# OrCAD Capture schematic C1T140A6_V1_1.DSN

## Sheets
1 000_NOTE: title: Telink-Semi; rev: V1.1; note: C1T140A6
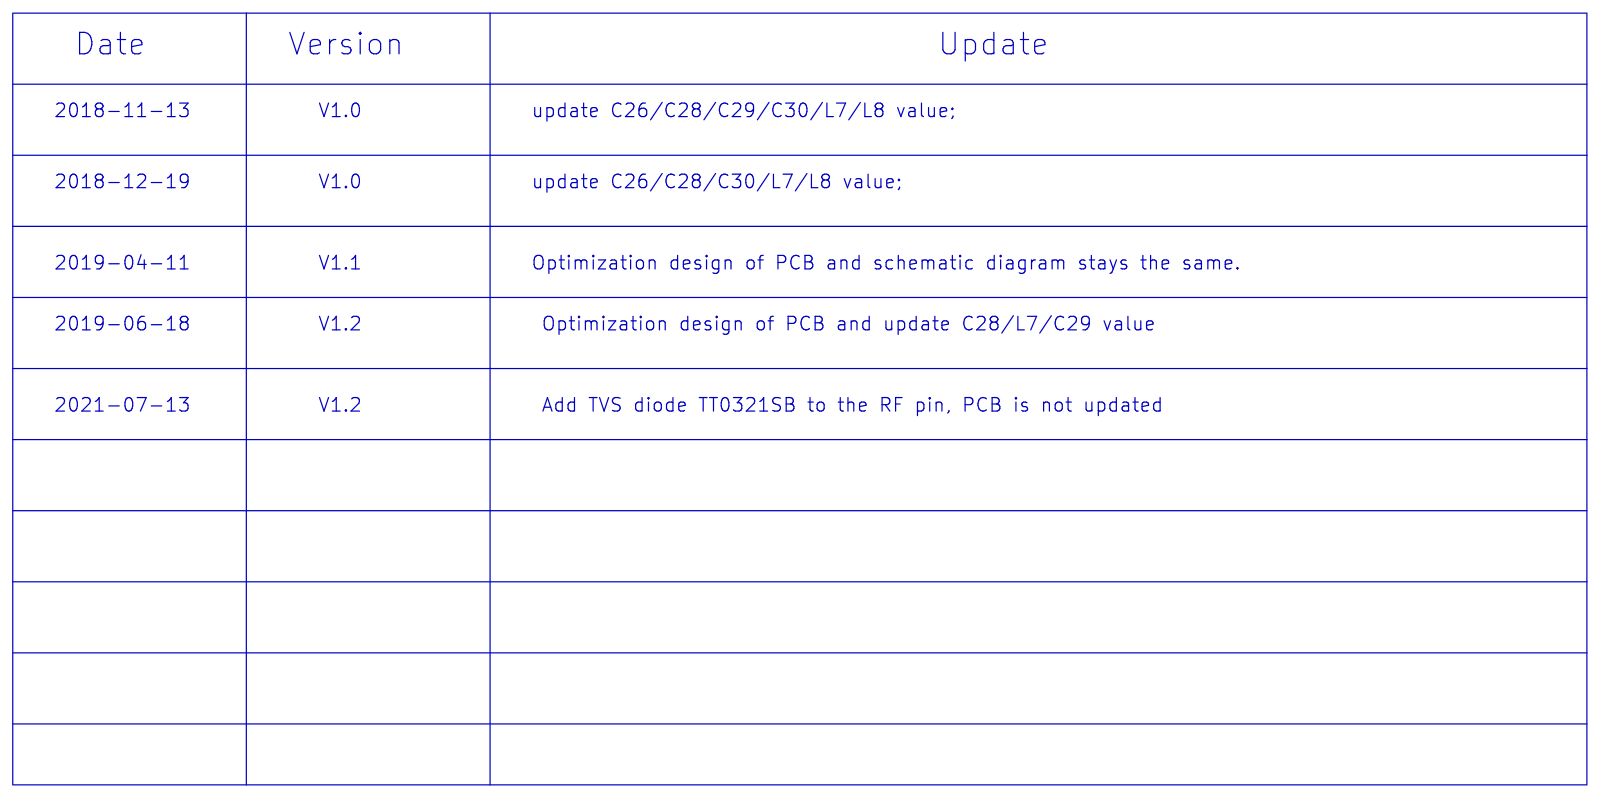
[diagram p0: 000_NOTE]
2 Main: size A4
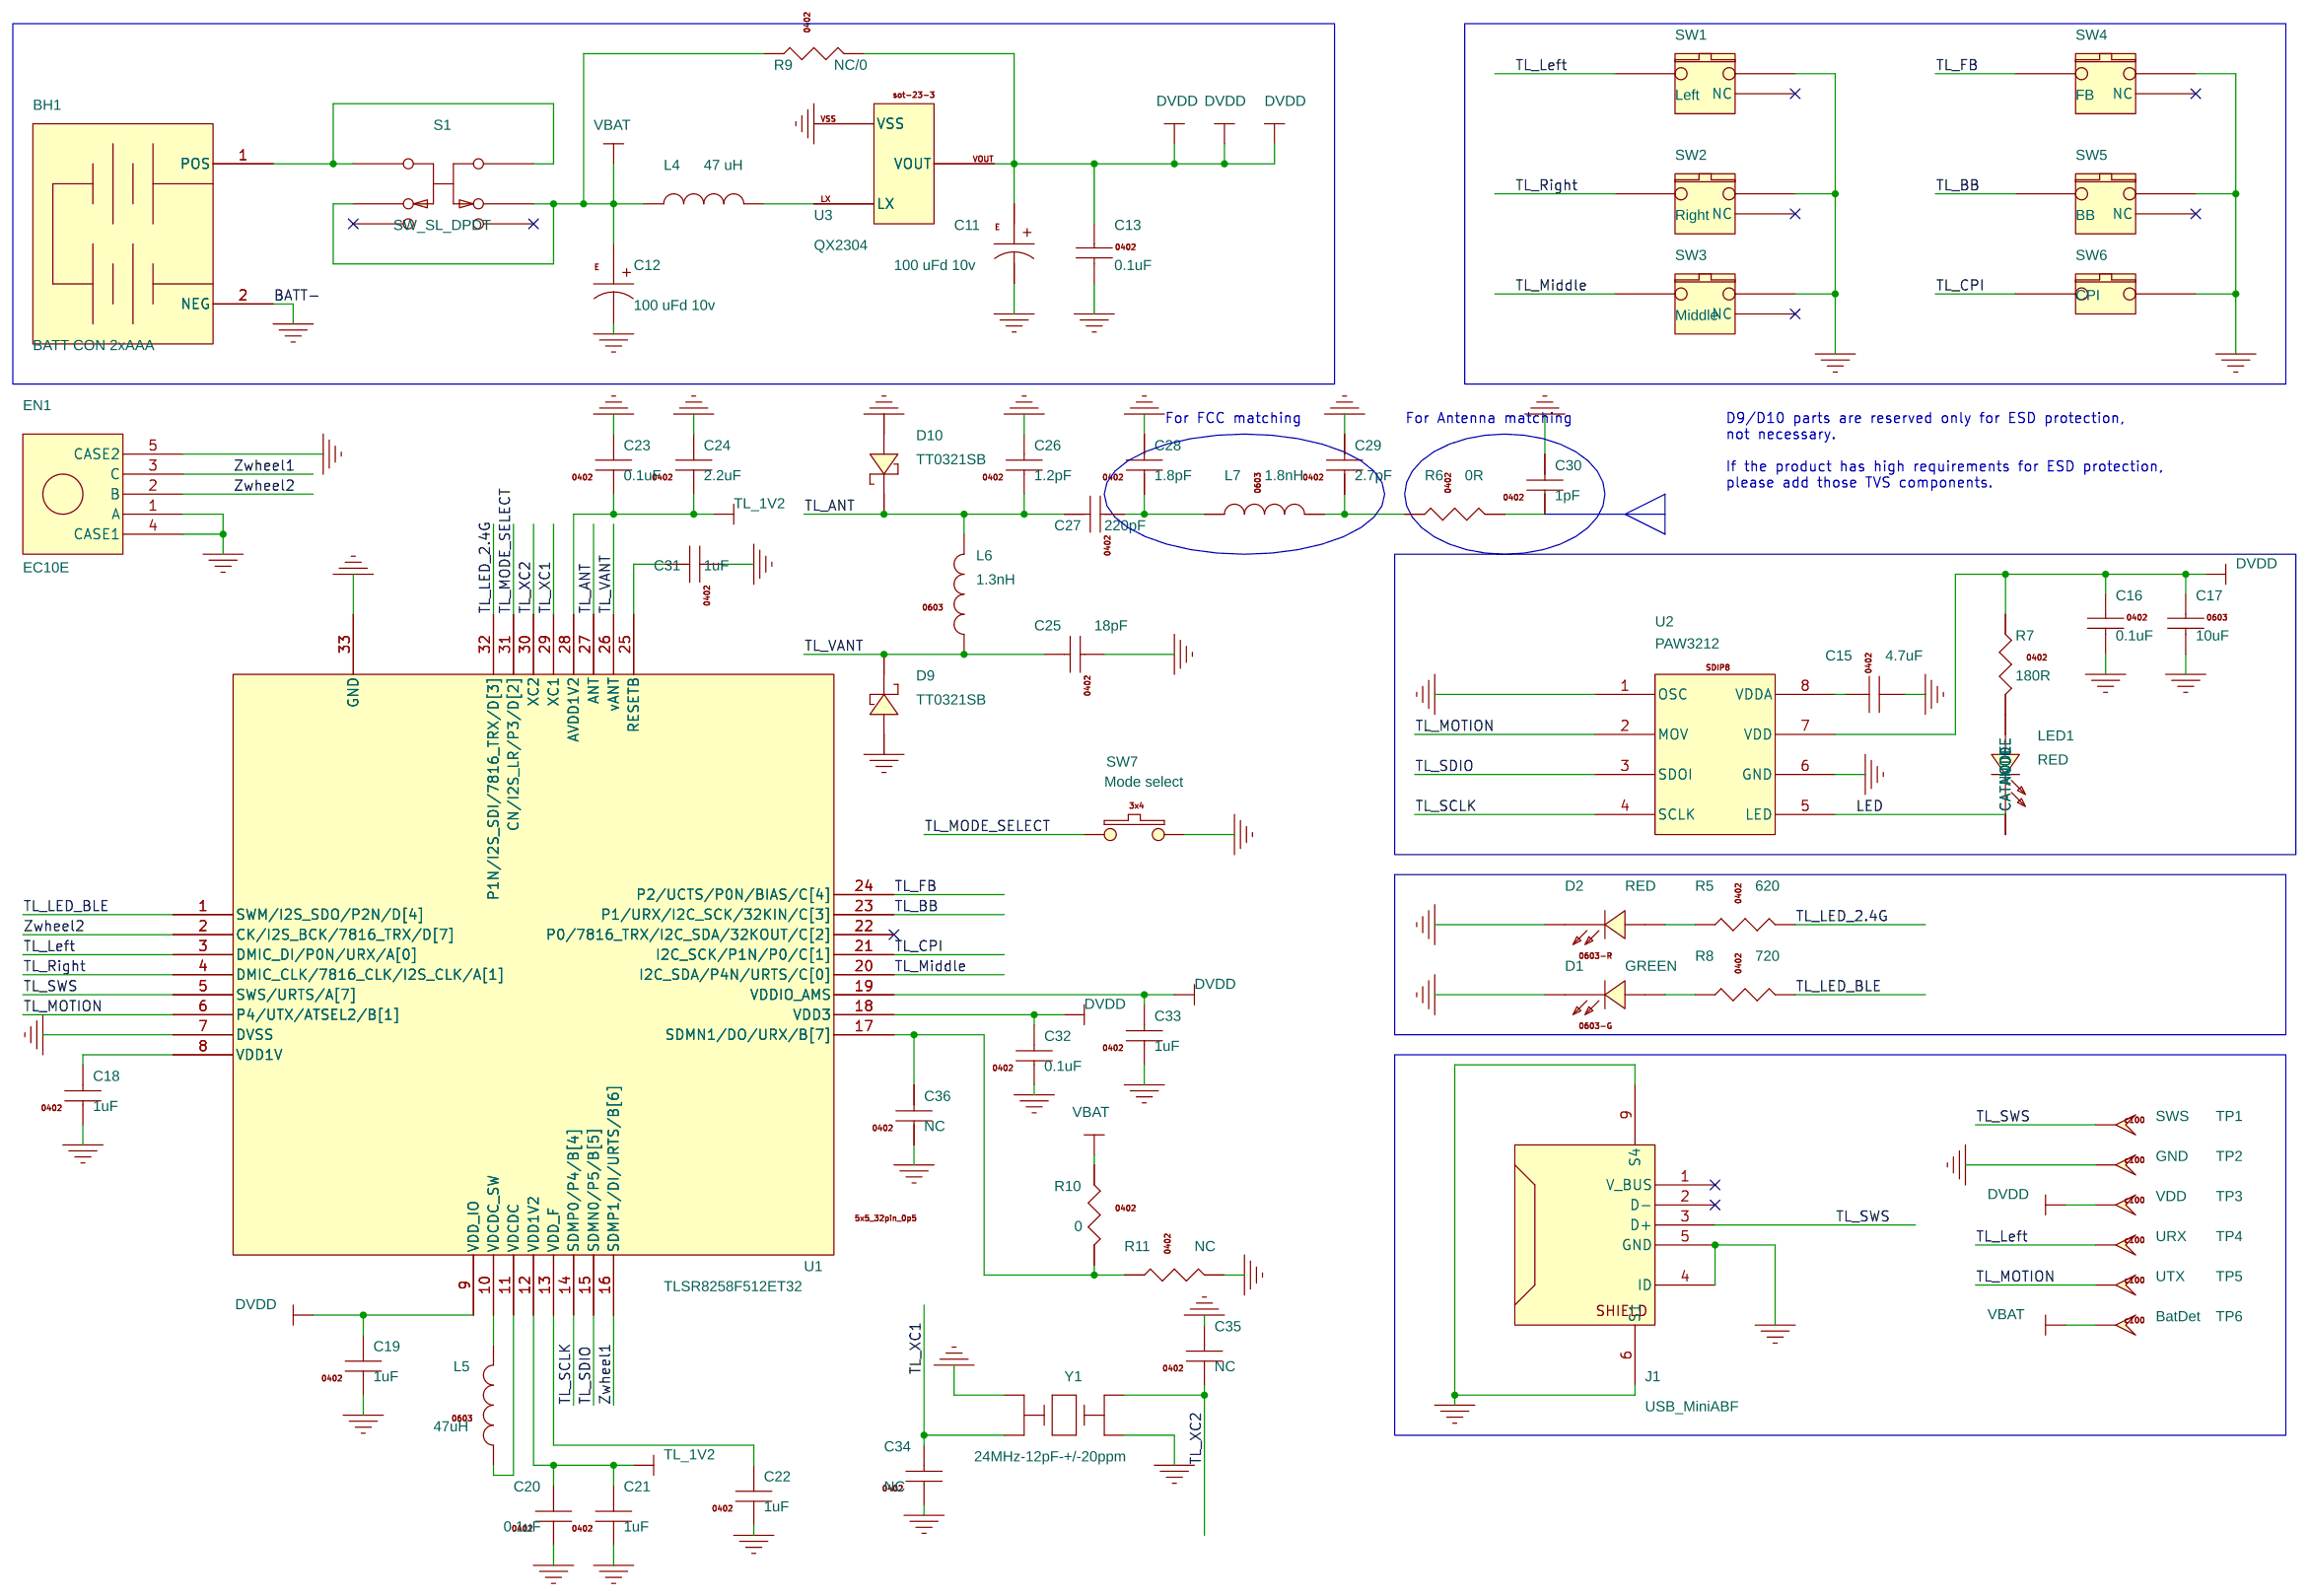
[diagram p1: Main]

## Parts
BH1  BATT CON 2xAAA  [BATT-HDR200F-2PIN]
C11  100 uFd 10v  [C-100uF10V-ELECT]
C12  100 uFd 10v  [C-100uF10V-ELECT]
C13  0.1uF  [0402]
C15  4.7uF  [0402]
C16  0.1uF  [0402]
C17  10uF  [0603C]
C18  1uF  [0402]
C19  1uF  [0402]
C20  0.1uF  [0402]
C21  1uF  [0402]
C22  1uF  [0402]
C23  0.1uF  [0402]
C24  2.2uF  [0402]
C25  18pF  [0402]
C26  1.2pF  [0402]
C27  220pF  [0402]
C28  1.8pF  [0402]
C29  2.7pF  [0402]
C30  1pF  [0402]
C31  1uF  [0402]
C32  0.1uF  [0402]
C33  1uF  [0402]
C34  NC  [0402]
C35  NC  [0402]
C36  NC  [0402]
D1  GREEN  [0603-LED]
D2  RED  [0603-LED]
D9  TT0321SB  [SOD-123]
D10  TT0321SB  [SOD-123]
EN1  EC10E  [ENCODER-BTC-MOUSE]
J1  USB_MiniABF  [hirose-us60-mb-5st_miniusb_7pin]
L4  47 uH  [L-TH-IND2MM]
L5  47uH  [0805L]
L6  1.3nH  [0402]
L7  1.8nH  [0402]
LED1  RED  [LED_TH_3MM_2PIN]
R5  620  [0402]
R6  0R  [0402]
R7  180R  [0402]
R8  720  [0402]
R9  NC/0  [0603R]
R10  0  [0402]
R11  NC  [0402]
S1  SW_SL_DPDT  [SW-TH-6PIN-3_60X9_00-34NP]
SW1  Left  [SW-Chicony-Mouse-3PIN-TH-3NP]
SW2  Right  [SW-Chicony-Mouse-3PIN-TH-3NP]
SW3  Middle  [SW-Chicony-Mouse-3PIN-TH-3NP]
SW4  FB  [SW-Chicony-Mouse-3PIN-TH-3NP]
SW5  BB  [SW-Chicony-Mouse-3PIN-TH-3NP]
SW6  CPI  [SW-Mouse-2PIN-TH]
SW7  Mode select  [butsmd2px4_00y3_00_nh]
TP1  SWS  [TP100]
TP2  GND  [TP100]
TP3  VDD  [TP100]
TP4  URX  [TP100]
TP5  UTX  [TP100]
TP6  BatDet  [TP100]
U1  TLSR8258F512ET32  [qfn_5x5_32pin_0p5_2p50x2p50]
U2  PAW3212  [sdip8-adns5030]
U3  QX2304  [qx2304_sot-23]
Y1  24MHz-12pF-+/-20ppm  [osccc200x250x080]

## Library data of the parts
BH1 = Chicony_Battery_conn_2xAA
C11 C12 = 100_uFd_Electrolytic_10v
C13 C16 = C1005X5R1C104K
C15 C18-C36 = C1005X5R1C105K
C17 = C1608X5R0J106M
D1 = 0603D_Green
D2 = 0603D_Red
D9 D10 = DIODE_SCHOTTKY_0
EN1 = EC10E
J1 = USB_MiniABF_0: PART: USB
L4 = 27_uH_Inductor_TH
L5-L7 = MLK1608_000R
LED1 = LED_5
R5 R6 R8 = RS0402K621JT
R7 R10 R11 = RS0402K181JT
R9 = RS0402K_34.8K_1%
S1 = SW_SL_DPDT
SW1 = Switch_Chicony_Mouse_3PIN_TH: DEVICE: SW_Left_MOUSE
SW2 = Switch_Chicony_Mouse_3PIN_TH: DEVICE: SW_Right_MOUSE
SW3 = Switch_Chicony_Mouse_3PIN_TH: DEVICE: SW_Middle_MOUSE
SW4 = Switch_Chicony_Mouse_3PIN_TH: DEVICE: SW_FB_MOUSE
SW5 = Switch_Chicony_Mouse_3PIN_TH: DEVICE: SW_BB_MOUSE
SW6 = Switch_Mouse_Button_2PIN: DEVICE: SW_CPI_BUTTON
SW7 = SW2PIN_3x4
TP1-TP6 = TestPad100
U1 = TLSR8258F512ET32
U2 = PAN3204UL
U3 = QX2304_SOT-23
Y1 = CRYSTAL4_SM_0

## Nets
AVDD: C11.1 C13.1 C16.1 C17.1 C19.2 C32.2 C33.2 R7.1 R9.2 TP3.1(TP) U1.9(VDD_IO) U1.18(VDD3) U1.19(VDDIO_AMS) U2.7(VDD) U3.3(VOUT)
GND: BH1.2(NEG) C11.2 C12.2 C13.2 C15.2 C16.2 C17.2 C18.1 C19.1 C20.1 C21.1 C22.1 C23.2 C24.2 C25.1 C26.2 C28.2 C29.2 C30.2 C31.1 C32.1 C33.1 C34.1 C35.2 C36.1 D1.C(CATHODE) D2.C(CATHODE) D9.A(ANODE) D10.A(ANODE) EN1.1(A) EN1.4(CASE1) EN1.5(CASE2) J1.4(ID) J1.5(GND) J1.6(S1) J1.9(S4) R11.2 SW1.1 SW2.1 SW3.1 SW4.1 SW5.1 SW6.2 SW7.2 TP2.1(TP) U1.7(DVSS) U1.33(GND) U2.1(OSC) U2.6(GND) U3.1(VSS) Y1.2 Y1.4
VBAT: C12.1 L4.1 R9.1 R10.1 S1.2 S1.5 TP6.1(TP)
LED: LED1.2(CATHODE) U2.5(LED)
TL_1V2: C20.2 C21.2 C23.1 C24.1 U1.12(VDD1V2) U1.28(AVDD1V2)
TL_ANT: C26.1 C27.2 D10.C(CATHODE) L6.2 U1.27(ANT)
TL_BB: SW5.2 U1.23(P1/URX/I2C_SCK/32KIN/C[3])
TL_CPI: SW6.1 U1.21(I2C_SCK/P1N/P0/C[1])
TL_FB: SW4.2 U1.24(P2/UCTS/P0N/BIAS/C[4])
TL_LED_2.4G: R5.2 U1.32(P1N/I2S_SDI/7816_TRX/D[3])
TL_LED_BLE: R8.2 U1.1(SWM/I2S_SDO/P2N/D[4])
TL_Left: SW1.2 TP4.1(TP) U1.3(DMIC_DI/P0N/URX/A[0])
TL_Middle: SW3.2 U1.20(I2C_SDA/P4N/URTS/C[0])
TL_MODE_SELECT: SW7.1 U1.31(CN/I2S_LR/P3/D[2])
TL_MOTION: TP5.1(TP) U1.6(P4/UTX/ATSEL2/B[1]) U2.2(MOV)
TL_Right: SW2.2 U1.4(DMIC_CLK/7816_CLK/I2S_CLK/A[1])
TL_SCLK: U1.14(SDMP0/P4/B[4]) U2.4(SCLK)
TL_SDIO: U1.15(SDMN0/P5/B[5]) U2.3(SDOI)
TL_SWS: J1.3(D+) TP1.1(TP) U1.5(SWS/URTS/A[7])
TL_VANT: C25.2 D9.C(CATHODE) L6.1 U1.26(vANT)
TL_XC1: C34.2 U1.29(XC1) Y1.3
TL_XC2: C35.1 U1.30(XC2) Y1.1
Zwheel1: EN1.3(C) U1.16(SDMP1/DI/URTS/B[6])
Zwheel2: EN1.2(B) U1.2(CK/I2S_BCK/7816_TRX/D[7])
N14408857: BH1.1(POS) S1.1 S1.6
N14408943: L4.2 U3.2(LX)
N14411039: C15.1 U2.8(VDDA)
N14476907: D2.A(ANODE) R5.1
N14481124: C36.2 R10.2 R11.1 U1.17(SDMN1/DO/URX/B[7])
N14481825: C18.2 U1.8(VDD1V)
N14482264: L5.2 U1.10(VDCDC_SW)
N14482268: L5.1 U1.11(VDCDC)
N14482755: C22.2 U1.13(VDD_F)
N14484292: C27.1 C28.1 L7.1
N14484554: C30.1 R6.2
N14485960: C31.2 U1.25(RESETB)
N14489122: D1.A(ANODE) R8.1
N14935989: C29.1 L7.2 R6.1
N14937002: LED1.1(ANODE) R7.2

Not connected (* = marked no-connect by the designer): J1 1(V_BUS)* 2(D-)*; S1 3* 4*; SW1 3(NC)*; SW2 3(NC)*; SW3 3(NC)*; SW4 3(NC)*; SW5 3(NC)*; U1 22(P0/7816_TRX/I2C_SDA/32KOUT/C[2])*

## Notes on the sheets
sheet 1
- Date
- Version
- Update
- 2018-11-13
- V1.0
- update C26/C28/C29/C30/L7/L8 value;
- 2018-12-19
- V1.0
- update C26/C28/C30/L7/L8 value;
- 2019-04-11
- V1.1
- Optimization design of PCB and schematic diagram stays the same.
- 2019-06-18
- V1.2
- Optimization design of PCB and update C28/L7/C29 value
- 2021-07-13
- V1.2
- Add TVS diode TT0321SB to the RF pin, PCB is not updated
sheet 2
- For FCC matching
- For Antenna matching
- D9/D10 parts are reserved only for ESD protection,
  not necessary.
  If the product has high requirements for ESD protection,
  please add those TVS components.
